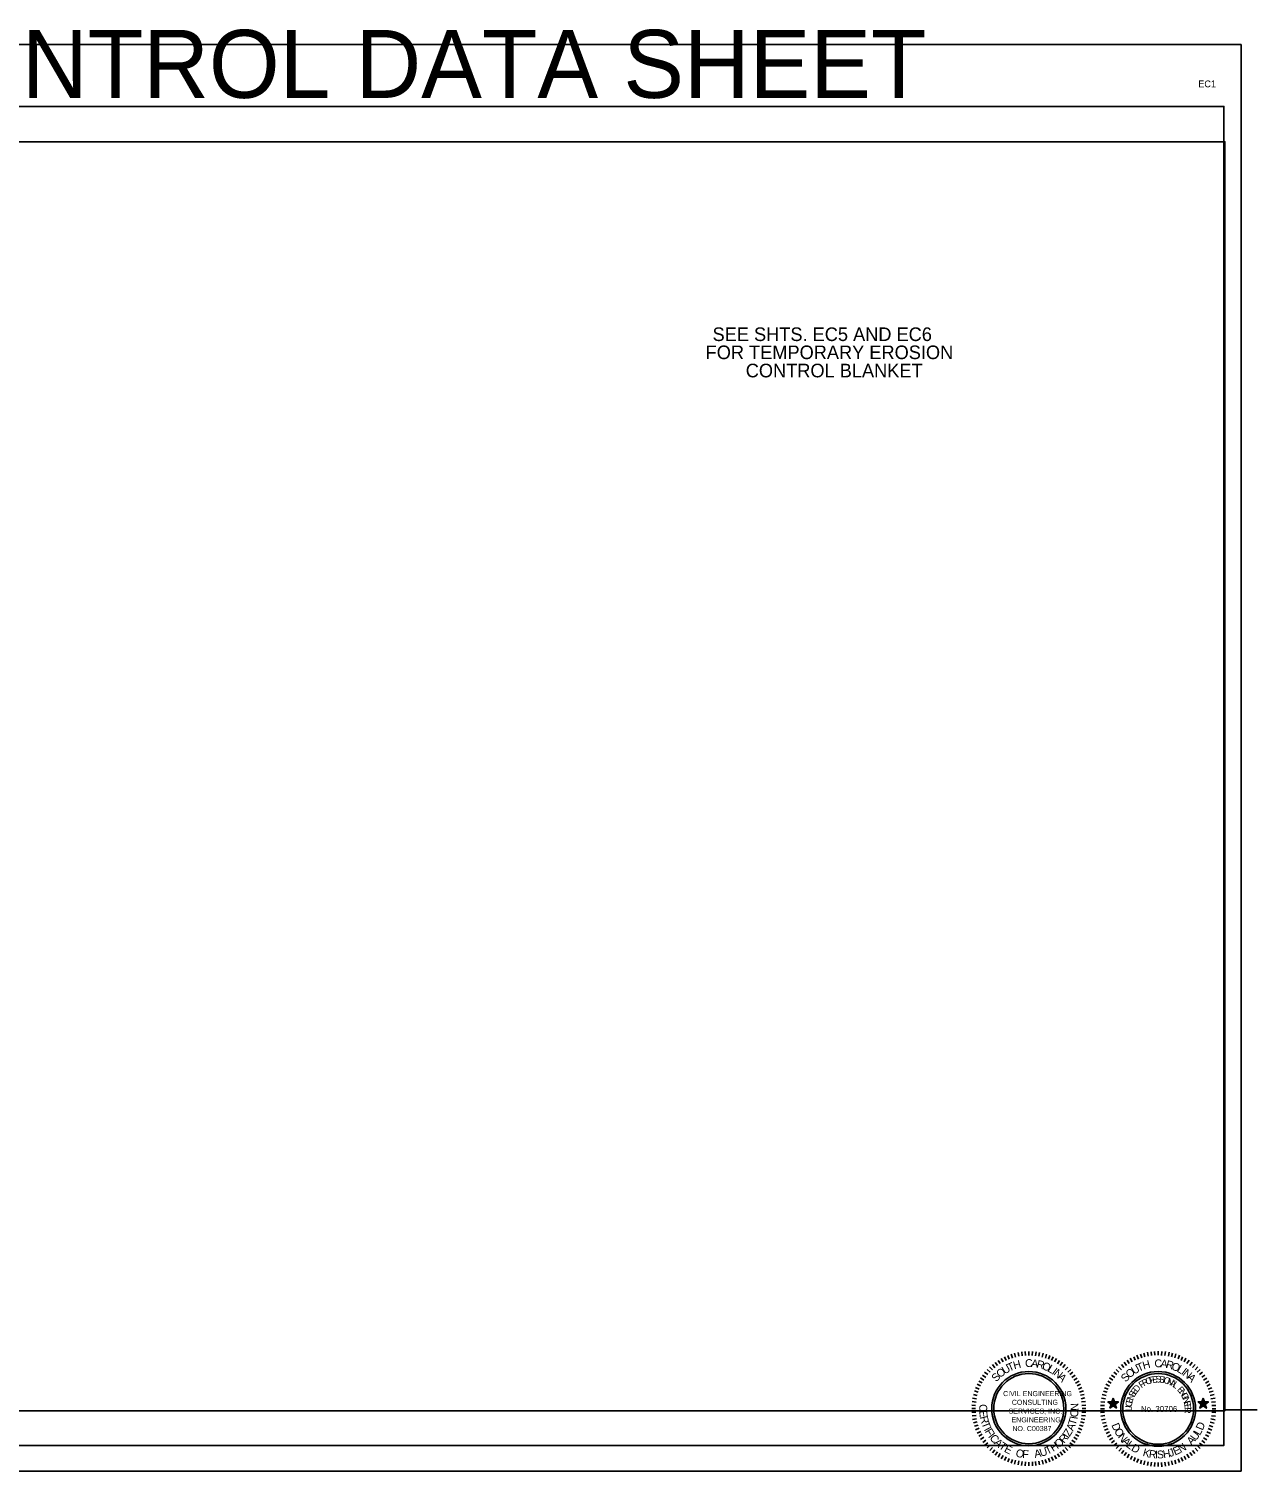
# Model space of a CAD drawing. Extents: x 260980 to 262786, y 322333 to 323393.
# Drawn here: x 261883 to 262786, y 322333 to 323393 of the extents above; entities that cross this region are included whole.
import ezdxf

# ---------------------------------------------------------------- set-up
doc = ezdxf.new("R2010")
doc.units = 0
for name, color, linetype in [('Level 2', 7, 'Continuous'), ('Level 23', 7, 'Continuous'), ('Level 3', 7, 'Continuous'), ('Level 8', 7, 'Continuous'), ('RD_SHT_SEAL_KA', 7, 'Continuous')]:
    doc.layers.add(name, color=color, linetype=linetype)

msp = doc.modelspace()

# ---------------------------------------------------------------- linework, layer by layer
at = {"layer": 'Level 2'}
msp.add_line((262762, 322377.8), (262786, 322377.8), dxfattribs=at)
at = {"layer": 'Level 23'}
msp.add_lwpolyline([(261111.1, 323336.4), (262761.5, 323336.4), (262761.5, 322351.8), (261111.1, 322351.8)], close=True, dxfattribs=at)
msp.add_lwpolyline([(261111.1, 323336.4), (262761.5, 323336.4), (262761.5, 322351.8), (261111.1, 322351.8)], close=True, dxfattribs=at)
at = {"layer": 'Level 3'}
for p, q in [((261099.2, 323381.9), (262774.2, 323381.9)), ((262774.2, 322332.8), (262774.2, 323381.9)), ((261099.2, 322332.9), (262774.2, 322332.9))]:
    msp.add_line(p, q, dxfattribs=at)
msp.add_lwpolyline([(261111.1, 322377.3), (262762.3, 322377.3), (262762.3, 323310.5), (261111.1, 323310.5)], close=True, dxfattribs=at)
at = {"layer": 'RD_SHT_SEAL_KA'}
for p, q in [((262600.2, 322416.8), (262601.5, 322414.2)), ((262602.7, 322417.9), (262603.7, 322415.2)), ((262605.1, 322418.8), (262606, 322416)), ((262607.7, 322419.5), (262608.3, 322416.7)), ((262610.3, 322420.2), (262610.8, 322417.3)), ((262612.9, 322420.5), (262613.3, 322417.7)), ((262615.5, 322420.8), (262615.7, 322417.9)), ((262618.2, 322420.9), (262618.2, 322418)), ((262620.8, 322420.8), (262620.6, 322417.9)), ((262623.4, 322420.5), (262623, 322417.7)), ((262626, 322420.1), (262625.5, 322417.4)), ((262628.6, 322419.5), (262627.9, 322416.7)), ((262631.1, 322418.8), (262630.3, 322416)), ((262633.6, 322417.9), (262632.6, 322415.2)), ((262636, 322416.8), (262634.8, 322414.2)), ((262692.7, 322415.8), (262694.2, 322413.2)), ((262695.2, 322417), (262696.4, 322414.4)), ((262697.6, 322418.1), (262698.7, 322415.3)), ((262700.1, 322418.9), (262701.1, 322416.2)), ((262702.6, 322419.7), (262703.4, 322416.9)), ((262705.3, 322420.3), (262705.8, 322417.4)), ((262708, 322420.6), (262708.3, 322417.8)), ((262710.6, 322420.9), (262710.7, 322418.1)), ((262713.3, 322421), (262713.2, 322418.2)), ((262715.8, 322420.9), (262715.6, 322417.9)), ((262718.6, 322420.7), (262718.2, 322417.8)), ((262721.2, 322420.3), (262720.7, 322417.5)), ((262723.8, 322419.7), (262723, 322416.9)), ((262726.3, 322419), (262725.5, 322416.2)), ((262728.9, 322418.1), (262727.8, 322415.4)), ((262731.2, 322417), (262730, 322414.3)), ((262733.6, 322415.8), (262732.3, 322413.3)), ((262585.6, 322405.6), (262587.9, 322403.8)), ((262587.5, 322407.5), (262589.7, 322405.6)), ((262589.3, 322409.5), (262591.4, 322407.4)), ((262591.4, 322411.3), (262593.1, 322408.9)), ((262593.4, 322412.8), (262595, 322410.6)), ((262595.6, 322414.3), (262597.1, 322411.9)), ((262597.8, 322415.7), (262599.2, 322413.1)), ((262638.4, 322415.7), (262636.9, 322413.2)), ((262640.7, 322414.2), (262639.1, 322411.8)), ((262642.8, 322412.9), (262641.1, 322410.5)), ((262644.9, 322411.2), (262643.2, 322409)), ((262646.9, 322409.4), (262644.9, 322407.4)), ((262648.9, 322407.6), (262646.7, 322405.6)), ((262650.5, 322405.6), (262648.3, 322403.8)), ((262680.5, 322405.6), (262682.8, 322403.8)), ((262682.3, 322407.5), (262684.4, 322405.6)), ((262684.1, 322409.5), (262686.2, 322407.4)), ((262686.2, 322411.3), (262688, 322409)), ((262688.3, 322412.9), (262690, 322410.6)), ((262690.5, 322414.4), (262692, 322412)), ((262736, 322414.4), (262734.4, 322412)), ((262738.2, 322412.9), (262736.5, 322410.5)), ((262740.3, 322411.3), (262738.4, 322409.1)), ((262742.3, 322409.5), (262740.4, 322407.4)), ((262744.2, 322407.6), (262742, 322405.6)), ((262745.9, 322405.6), (262743.7, 322403.8)), ((262580.1, 322396.7), (262582.6, 322395.5)), ((262581.3, 322399), (262583.7, 322397.7)), ((262582.6, 322401.4), (262585.1, 322399.8)), ((262584.1, 322403.5), (262586.4, 322401.8)), ((262652.2, 322403.5), (262649.8, 322401.8)), ((262653.7, 322401.3), (262651.2, 322399.8)), ((262655.1, 322399.1), (262652.5, 322397.6)), ((262656.1, 322396.7), (262653.7, 322395.5)), ((262674.8, 322396.7), (262677.4, 322395.4)), ((262676.1, 322399), (262678.6, 322397.6)), ((262677.4, 322401.4), (262679.9, 322399.8)), ((262678.9, 322403.5), (262681.3, 322401.8)), ((262747.5, 322403.5), (262745.2, 322401.9)), ((262749.1, 322401.3), (262746.6, 322399.8)), ((262750.4, 322399), (262747.9, 322397.6)), ((262751.5, 322396.7), (262749, 322395.4)), ((262576.4, 322384), (262579.3, 322383.6)), ((262576.8, 322386.6), (262579.7, 322386.1)), ((262577.4, 322389.2), (262580.2, 322388.4)), ((262578.1, 322391.8), (262580.9, 322390.9)), ((262579, 322394.3), (262581.6, 322393.2)), ((262657.2, 322394.3), (262654.6, 322393.2)), ((262658.2, 322391.8), (262655.4, 322390.9)), ((262658.9, 322389.2), (262656.1, 322388.6)), ((262659.4, 322386.7), (262656.6, 322386.1)), ((262659.9, 322384.1), (262656.9, 322383.7)), ((262671.6, 322386.5), (262674.4, 322386)), ((262672.1, 322389.1), (262675, 322388.4)), ((262672.9, 322391.7), (262675.6, 322390.8)), ((262673.8, 322394.2), (262676.5, 322393.1)), ((262752.7, 322394.2), (262750, 322393.2)), ((262753.6, 322391.7), (262750.8, 322390.8)), ((262754.4, 322389.2), (262751.5, 322388.5)), ((262755, 322386.6), (262752, 322386)), ((262576.2, 322381.3), (262579, 322381.2)), ((262576.2, 322378.8), (262579, 322378.8)), ((262576.2, 322376.1), (262579.1, 322376.3)), ((262576.4, 322373.5), (262579.3, 322373.8)), ((262659.9, 322373.5), (262656.9, 322373.8)), ((262660.1, 322381.4), (262657.2, 322381.2)), ((262660.1, 322376.1), (262657.2, 322376.3)), ((262660.1, 322378.8), (262657.4, 322378.8)), ((262670.9, 322381.2), (262673.8, 322381.1)), ((262670.9, 322378.6), (262673.7, 322378.6)), ((262670.9, 322375.9), (262673.7, 322376.1)), ((262671.1, 322383.9), (262674, 322383.6)), ((262671.1, 322373.2), (262674.1, 322373.7)), ((262755.3, 322373.3), (262752.4, 322373.6)), ((262755.4, 322383.9), (262752.5, 322383.6)), ((262755.5, 322381.2), (262752.7, 322381.1)), ((262755.5, 322376), (262752.7, 322376.2)), ((262755.7, 322378.6), (262752.8, 322378.6)), ((262576.8, 322370.9), (262579.6, 322371.4)), ((262577.4, 322368.3), (262580.1, 322369)), ((262578.2, 322365.8), (262580.9, 322366.6)), ((262579, 322363.2), (262581.7, 322364.4)), ((262657.2, 322363.3), (262654.6, 322364.4)), ((262658.1, 322365.8), (262655.3, 322366.6)), ((262658.9, 322368.3), (262656.1, 322369)), ((262659.4, 322370.8), (262656.6, 322371.4)), ((262671.5, 322370.6), (262674.3, 322371.1)), ((262672.2, 322368), (262674.9, 322368.7)), ((262672.9, 322365.5), (262675.6, 322366.4)), ((262673.7, 322363), (262676.5, 322364)), ((262752.7, 322363), (262749.9, 322364.1)), ((262753.5, 322365.5), (262750.8, 322366.4)), ((262754.4, 322368.1), (262751.5, 322368.8)), ((262755, 322370.6), (262752, 322371.2)), ((262580.1, 322360.8), (262582.8, 322362.1)), ((262581.3, 322358.5), (262583.7, 322360)), ((262582.6, 322356.2), (262585.1, 322357.8)), ((262584.2, 322353.9), (262586.4, 322355.7)), ((262585.7, 322352), (262587.9, 322353.7)), ((262650.6, 322351.9), (262648.3, 322353.7)), ((262652.1, 322353.9), (262649.8, 322355.7)), ((262653.7, 322356.1), (262651.2, 322357.7)), ((262655, 322358.5), (262652.4, 322359.9)), ((262656.2, 322360.9), (262653.6, 322362.1)), ((262674.9, 322360.5), (262677.5, 322361.8)), ((262676, 322358.1), (262678.6, 322359.6)), ((262677.5, 322355.8), (262679.8, 322357.4)), ((262678.9, 322353.6), (262681.2, 322355.4)), ((262680.5, 322351.6), (262682.8, 322353.4)), ((262746, 322351.6), (262743.7, 322353.4)), ((262747.6, 322353.6), (262745.2, 322355.3)), ((262749.1, 322355.8), (262746.6, 322357.3)), ((262750.4, 322358.2), (262747.9, 322359.5)), ((262751.6, 322360.5), (262749, 322361.8)), ((262587.5, 322350), (262589.7, 322351.9)), ((262589.4, 322348.1), (262591.4, 322350.2)), ((262591.4, 322346.3), (262593.1, 322348.5)), ((262593.4, 322344.7), (262595.1, 322347)), ((262595.6, 322343.2), (262597.1, 322345.7)), ((262597.9, 322341.9), (262599.3, 322344.3)), ((262600.2, 322340.6), (262601.4, 322343.4)), ((262602.6, 322339.6), (262603.7, 322342.2)), ((262605.1, 322338.7), (262606, 322341.5)), ((262633.6, 322339.6), (262632.5, 322342.3)), ((262636.1, 322340.7), (262634.8, 322343.3)), ((262638.4, 322341.9), (262637.1, 322344.3)), ((262640.6, 322343.3), (262639.1, 322345.6)), ((262642.8, 322344.7), (262641.2, 322347)), ((262644.9, 322346.3), (262643.2, 322348.5)), ((262646.9, 322348.1), (262644.9, 322350.2)), ((262648.8, 322350), (262646.7, 322351.9)), ((262682.3, 322349.5), (262684.4, 322351.5)), ((262684.3, 322347.6), (262686.2, 322349.7)), ((262686.2, 322345.9), (262688, 322348.1)), ((262688.3, 322344.3), (262690, 322346.6)), ((262690.5, 322342.7), (262692, 322345.2)), ((262692.8, 322341.4), (262694.2, 322343.9)), ((262695.2, 322340.2), (262696.4, 322342.8)), ((262697.5, 322339.1), (262698.7, 322341.8)), ((262728.9, 322339.1), (262727.8, 322341.8)), ((262731.4, 322340.2), (262730.1, 322342.8)), ((262733.6, 322341.4), (262732.3, 322343.9)), ((262735.9, 322342.7), (262734.4, 322345.2)), ((262738.2, 322344.3), (262736.5, 322346.6)), ((262740.2, 322345.9), (262738.4, 322348.1)), ((262742.3, 322347.6), (262740.3, 322349.8)), ((262744.2, 322349.5), (262742.1, 322351.5)), ((262607.7, 322338), (262608.3, 322340.8)), ((262610.3, 322337.4), (262610.7, 322340.3)), ((262612.8, 322336.9), (262613.3, 322339.9)), ((262615.5, 322336.7), (262615.7, 322339.7)), ((262618.2, 322336.7), (262618.1, 322339.5)), ((262620.8, 322336.7), (262620.7, 322339.7)), ((262623.3, 322337), (262623, 322339.9)), ((262625.9, 322337.4), (262625.5, 322340.2)), ((262628.6, 322338), (262627.9, 322340.8)), ((262631.1, 322338.7), (262630.2, 322341.4)), ((262700.1, 322338.2), (262701, 322341)), ((262702.7, 322337.4), (262703.3, 322340.3)), ((262705.3, 322336.9), (262705.8, 322339.8)), ((262707.9, 322336.5), (262708.3, 322339.4)), ((262710.6, 322336.2), (262710.8, 322339.1)), ((262713.3, 322336.2), (262713.3, 322339.1)), ((262715.9, 322336.1), (262715.7, 322339.2)), ((262718.5, 322336.5), (262718.2, 322339.4)), ((262721.1, 322336.9), (262720.7, 322339.8)), ((262723.8, 322337.5), (262723.1, 322340.3)), ((262726.3, 322338.2), (262725.5, 322340.9))]:
    msp.add_line(p, q, dxfattribs=at)
for points in [[(262680.2, 322386.5), (262679.2, 322383.7), (262676.3, 322383.7), (262678.7, 322381.9), (262677.7, 322379.2), (262680.2, 322380.9), (262682.5, 322379.2), (262681.6, 322381.9), (262684, 322383.7), (262681.1, 322383.7)], [(262680.1, 322386.1), (262679.4, 322383.6), (262676.7, 322383.6), (262678.8, 322382), (262678, 322379.4), (262680.1, 322381.1), (262682.3, 322379.4), (262681.5, 322382), (262683.7, 322383.6), (262681, 322383.6)], [(262680.2, 322385.7), (262679.4, 322383.4), (262677, 322383.4), (262679, 322382), (262678.3, 322379.8), (262680.2, 322381.2), (262682.1, 322379.7), (262681.3, 322382.1), (262683.3, 322383.4), (262680.9, 322383.4)], [(262680.2, 322385.3), (262679.5, 322383.3), (262677.4, 322383.3), (262679.1, 322382.1), (262678.5, 322380.1), (262680.1, 322381.3), (262681.9, 322380.1), (262681.3, 322382.1), (262682.9, 322383.4), (262680.8, 322383.3)], [(262680.2, 322385), (262679.6, 322383.2), (262677.8, 322383.2), (262679.2, 322382.1), (262678.6, 322380.4), (262680.2, 322381.5), (262681.7, 322380.4), (262681.1, 322382.1), (262682.5, 322383.2), (262680.8, 322383.2)], [(262680.2, 322384.6), (262679.7, 322383.1), (262678.2, 322383.1), (262679.4, 322382.2), (262678.9, 322380.7), (262680.2, 322381.7), (262681.5, 322380.7), (262680.9, 322382.2), (262682.2, 322383), (262680.6, 322383.1)], [(262680.2, 322384.1), (262679.8, 322383), (262678.5, 322382.8), (262679.6, 322382.3), (262679.2, 322381.1), (262680.1, 322381.8), (262681.2, 322381), (262680.9, 322382.3), (262681.8, 322383), (262680.5, 322383)], [(262746.3, 322386.5), (262745.3, 322383.7), (262742.5, 322383.7), (262744.9, 322381.9), (262743.9, 322379.1), (262746.3, 322380.9), (262748.7, 322379.1), (262747.7, 322381.9), (262750.1, 322383.7), (262747.2, 322383.7)], [(262746.3, 322386.1), (262745.4, 322383.6), (262742.8, 322383.6), (262745, 322381.9), (262744.2, 322379.4), (262746.3, 322381), (262748.5, 322379.4), (262747.7, 322382), (262749.8, 322383.6), (262747.1, 322383.6)], [(262746.3, 322385.7), (262745.6, 322383.4), (262743.2, 322383.4), (262745.1, 322382), (262744.4, 322379.7), (262746.3, 322381.2), (262748.3, 322379.8), (262747.5, 322382), (262749.4, 322383.5), (262747.1, 322383.4)], [(262746.3, 322385.3), (262745.7, 322383.3), (262743.6, 322383.3), (262745.3, 322382.1), (262744.5, 322380.1), (262746.3, 322381.3), (262748, 322380.1), (262747.3, 322382.1), (262749.1, 322383.3), (262747, 322383.3)], [(262746.3, 322384.9), (262745.7, 322383.2), (262743.9, 322383.2), (262745.3, 322382.2), (262744.9, 322380.4), (262746.3, 322381.4), (262747.7, 322380.4), (262747.2, 322382.1), (262748.7, 322383.2), (262746.9, 322383.2)], [(262746.4, 322384.5), (262745.8, 322383.1), (262744.3, 322383.1), (262745.6, 322382.3), (262745, 322380.7), (262746.3, 322381.6), (262747.5, 322380.7), (262747.1, 322382.1), (262748.3, 322383.1), (262746.8, 322383.1)], [(262746.3, 322384.1), (262745.9, 322383), (262744.6, 322383), (262745.7, 322382.2), (262745.3, 322381.1), (262746.3, 322381.8), (262747.3, 322381), (262746.9, 322382.3), (262748, 322383), (262746.7, 322383)], [(262680.2, 322383.8), (262679.9, 322382.8), (262678.9, 322382.8), (262679.7, 322382.3), (262679.4, 322381.4), (262680.2, 322381.9), (262681, 322381.3), (262680.7, 322382.3), (262681.5, 322382.8), (262680.4, 322382.9)], [(262680.2, 322383.3), (262679.9, 322382.7), (262679.2, 322382.7), (262679.8, 322382.3), (262679.7, 322381.7), (262680.2, 322382.1), (262680.6, 322381.7), (262680.5, 322382.3), (262681.1, 322382.7), (262680.4, 322382.7)], [(262680.2, 322383), (262680, 322382.6), (262679.7, 322382.6), (262680, 322382.4), (262679.8, 322382), (262680.2, 322382.3), (262680.4, 322382), (262680.3, 322382.4), (262680.6, 322382.6), (262680.3, 322382.6)], [(262680.2, 322382.6), (262680.2, 322382.4), (262679.9, 322382.5), (262680.1, 322382.5), (262680.1, 322382.3), (262680.2, 322382.3), (262680.2, 322382.3), (262680.2, 322382.4), (262680.4, 322382.5), (262680.2, 322382.5)], [(262746.3, 322383.7), (262746, 322382.8), (262745, 322382.8), (262745.8, 322382.3), (262745.5, 322381.4), (262746.3, 322381.9), (262747.1, 322381.3), (262746.8, 322382.3), (262747.5, 322382.8), (262746.6, 322382.8)], [(262746.3, 322383.4), (262746, 322382.7), (262745.4, 322382.7), (262745.9, 322382.4), (262745.7, 322381.7), (262746.3, 322382), (262746.9, 322381.7), (262746.6, 322382.3), (262747.2, 322382.7), (262746.6, 322382.7)], [(262746.3, 322383), (262746.2, 322382.6), (262745.8, 322382.6), (262746.1, 322382.4), (262745.9, 322382), (262746.4, 322382.2), (262746.6, 322382), (262746.5, 322382.3), (262746.9, 322382.6), (262746.5, 322382.6)], [(262746.4, 322382.6), (262746.3, 322382.5), (262746.1, 322382.5), (262746.2, 322382.4), (262746.2, 322382.3), (262746.3, 322382.4), (262746.4, 322382.4), (262746.4, 322382.4), (262746.4, 322382.5), (262746.3, 322382.4)]]:
    msp.add_lwpolyline(points, close=True, dxfattribs=at)
for radius in [27.5, 26]:
    msp.add_circle((262713.2, 322378.6), radius, dxfattribs=at)
for major_axis in [(0, 27.3), (0, 25.8)]:
    msp.add_ellipse((262618.1, 322378.8), major_axis=major_axis, ratio=0.998589, dxfattribs=at)

# ---------------------------------------------------------------- texts
at = {"layer": 'Level 3'}
for s, height, p in [('EC1', 5, (262742.7, 323350.5)), ('SEE SHTS. EC5 AND EC6', 10, (262385.6, 323163.9)), ('FOR TEMPORARY EROSION', 10, (262380.5, 323150.6)), ('CONTROL BLANKET', 10, (262410, 323137.2))]:
    msp.add_text(s, height=height, dxfattribs=at).set_placement(p)
at = {"layer": 'Level 8'}
msp.add_text('EROSION CONTROL DATA SHEET', height=50, dxfattribs=at).set_placement((261450.7, 323342.7))
at = {"layer": 'RD_SHT_SEAL_KA'}
for s, height, rotation, p in [('O', 5.79, 39.0332, (262597, 322401.1)), ('U', 5.79, 30.8031, (262600.4, 322403.9)), ('T', 5.79, 23.2887, (262603.8, 322406)), ('H', 5.79, 15.7743, (262607.5, 322407.6)), ('C', 5.79, 0.6858, (262615.4, 322409.4)), ('A', 5.79, 352.8136, (262619.6, 322409.5)), ('R', 5.79, 345.657, (262623.4, 322409.1)), ('O', 5.79, 338.1426, (262627.3, 322408.1)), ('L', 5.79, 329.9125, (262631.4, 322406.5)), ('I', 5.79, 323.1138, (262634.6, 322404.7)), ('N', 5.79, 320.609, (262635.8, 322404)), ('O', 5.79, 39.0332, (262692.1, 322400.9)), ('U', 5.79, 30.8031, (262695.5, 322403.7)), ('T', 5.79, 23.2887, (262698.9, 322405.8)), ('H', 5.79, 15.7743, (262702.6, 322407.5)), ('C', 5.79, 0.6858, (262710.5, 322409.2)), ('A', 5.79, 352.8136, (262714.7, 322409.3)), ('R', 5.79, 345.657, (262718.5, 322408.9)), ('O', 5.79, 338.1426, (262722.4, 322407.9)), ('L', 5.79, 329.9125, (262726.5, 322406.3)), ('I', 5.79, 323.1138, (262729.7, 322404.6)), ('N', 5.79, 320.609, (262730.8, 322403.8)), ('S', 5.79, 46.5476, (262594.2, 322398.1)), ('A', 5.79, 313.0946, (262638.9, 322401.5)), ('S', 5.79, 46.5476, (262689.3, 322397.9)), ('D', 4.82, 48.9361, (262697.7, 322390.4)), ('P', 4.82, 35.3308, (262700.9, 322393.7)), ('R', 4.82, 28.555, (262702.8, 322395)), ('O', 4.82, 21.7793, (262704.8, 322396.1)), ('F', 4.82, 14.3582, (262707.1, 322397.1)), ('E', 4.82, 7.9051, (262709.2, 322397.6)), ('S', 4.82, 1.452, (262711.4, 322398)), ('S', 4.82, 354.6762, (262713.7, 322398)), ('I', 4.82, 347.9004, (262716, 322397.8)), ('O', 4.82, 345.6418, (262716.8, 322397.7)), ('N', 4.82, 338.2207, (262719.2, 322397.1)), ('A', 4.82, 331.445, (262721.3, 322396.3)), ('L', 4.82, 324.9919, (262723.3, 322395.2)), ('E', 4.82, 312.0319, (262726.8, 322392.5)), ('A', 5.79, 313.0946, (262734, 322401.3)), ('CIVIL ENGINEERING', 3.751, 359.9897, (262599.2, 322388)), ('CONSULTING', 3.75, 359.9897, (262605.6, 322381.6)), ('C', 4.82, 82.4923, (262693.8, 322379.8)), ('E', 4.82, 75.3939, (262694.1, 322382.2)), ('N', 4.82, 68.9407, (262694.6, 322384.3)), ('S', 4.82, 62.165, (262695.4, 322386.5)), ('E', 4.82, 55.3892, (262696.5, 322388.5)), ('N', 4.82, 305.5788, (262728.2, 322390.9)), ('G', 4.82, 298.803, (262729.6, 322389.1)), ('I', 4.82, 291.7046, (262730.8, 322387)), ('N', 4.82, 289.446, (262731.1, 322386.3)), ('E', 4.82, 282.6702, (262731.9, 322384.1)), ('C', 5.79, 268.515, (262581.8, 322382.2)), ('E', 5.79, 276.3872, (262581.6, 322377.2)), ('R', 5.79, 283.5438, (262582.1, 322372.7)), ('SERVICES, INC.', 3.751, 359.9897, (262603.2, 322375.1)), ('O', 5.79, 83.6128, (262654.1, 322372.2)), ('N', 5.79, 91.8428, (262654.7, 322377.4)), ('I', 4.82, 84.7509, (262693.7, 322379.1)), ('L', 4.82, 90.8813, (262693.8, 322377)), ('E', 4.82, 276.2171, (262732.4, 322382)), ('R', 4.82, 269.764, (262732.6, 322379.8)), ('T', 5.79, 291.0582, (262583.2, 322368)), ('I', 5.79, 298.5727, (262584.9, 322363.5)), ('F', 5.79, 301.0775, (262585.6, 322362.1)), ('ENGINEERING', 3.751, 359.9897, (262605.4, 322368.7)), ('NO. C00387', 3.75, 359.9897, (262606, 322362.3)), ('Z', 5.79, 58.9225, (262648.1, 322357.8)), ('A', 5.79, 66.437, (262650.6, 322361.9)), ('T', 5.79, 73.5935, (262652.4, 322366.1)), ('I', 5.79, 81.108, (262653.8, 322370.7)), ('D', 5.78, 292.563, (262678.7, 322366.8)), ('O', 5.78, 300.0892, (262680.6, 322362.4)), ('D', 5.78, 67.437, (262745.9, 322362.4)), ('I', 5.79, 308.234, (262587.9, 322358.2)), ('C', 5.79, 310.7388, (262588.9, 322356.9)), ('A', 5.79, 318.6111, (262592.1, 322353.1)), ('T', 5.79, 325.7677, (262595.6, 322350)), ('E', 5.79, 333.2821, (262599.5, 322347.3)), ('H', 5.79, 33.1588, (262636, 322346.9)), ('O', 5.79, 40.6733, (262640, 322349.5)), ('R', 5.79, 48.9033, (262644, 322352.9)), ('I', 5.79, 56.4177, (262647.1, 322356.5)), ('N', 5.78, 308.3321, (262683.2, 322357.9)), ('A', 5.78, 315.8583, (262686.2, 322354.1)), ('L', 5.78, 323.0261, (262689.4, 322351)), ('D', 5.78, 329.8355, (262692.9, 322348.3)), ('N', 5.78, 30.8215, (262729.8, 322346.1)), ('A', 5.78, 45.9336, (262737.7, 322351.6)), ('U', 5.78, 53.1014, (262740.9, 322354.8)), ('L', 5.78, 60.6276, (262743.8, 322358.7)), ('O', 5.79, 348.0127, (262608.1, 322343.6)), ('F', 5.79, 356.2428, (262613.2, 322342.6)), ('A', 5.79, 10.9734, (262622.6, 322342.5)), ('U', 5.79, 18.13, (262627.1, 322343.3)), ('T', 5.79, 25.6444, (262631.7, 322344.8)), ('K', 5.78, 344.9476, (262701.5, 322344.1)), ('R', 5.78, 352.4738, (262706.1, 322342.8)), ('I', 5.78, 360, (262710.8, 322342.2)), ('S', 5.78, 2.5087, (262712.4, 322342.1)), ('H', 5.78, 10.0349, (262717.2, 322342.3)), ('J', 5.78, 17.5611, (262721.9, 322343.2)), ('E', 5.78, 23.6537, (262725.6, 322344.3))]:
    msp.add_text(s, height=height, rotation=rotation, dxfattribs=at).set_placement(p)
msp.add_text('No. 30706', height=4.34, dxfattribs=at).set_placement((262700.5, 322376.4))

doc.saveas('drawing.dxf')
